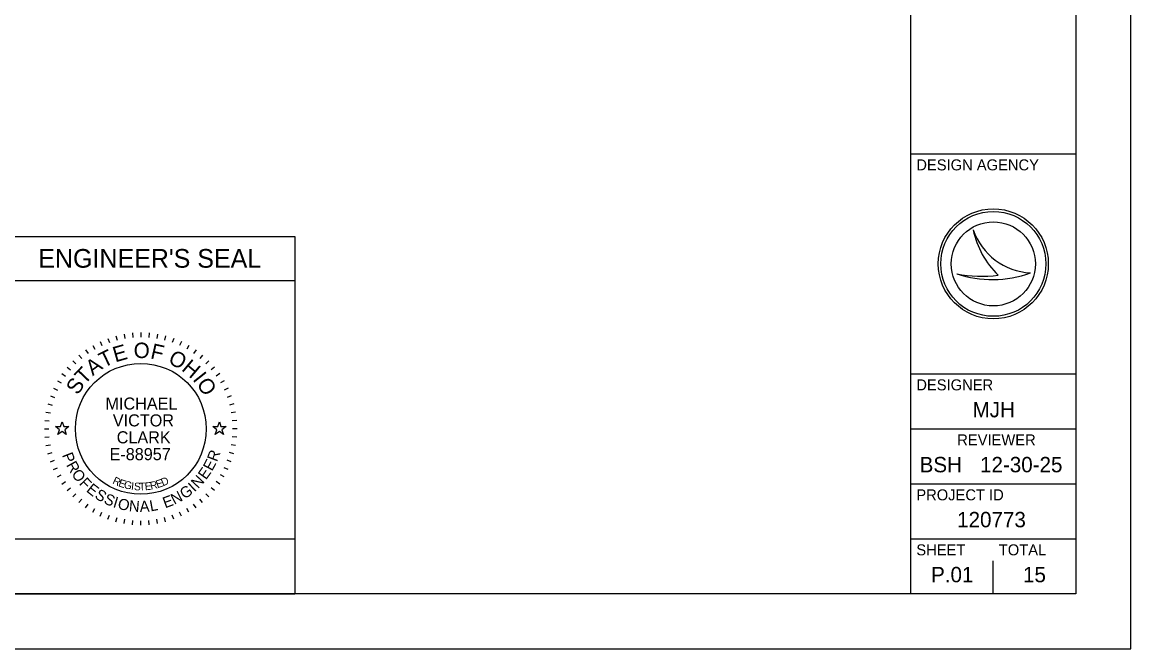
# Model space of a CAD drawing. Extents: x -7.9 to 76.1, y 0 to 22.
# Drawn here: x 23.92 to 34, y 0 to 5.7 of the extents above; entities that cross this region are included whole.
import ezdxf

# ---------------------------------------------------------------- set-up
doc = ezdxf.new("R2010")
doc.units = 0
for name, color, linetype in [('Default', 7, 'Continuous'), ('SH_Border', 7, 'Continuous'), ('SH_Cut_Line', 7, 'Continuous'), ('SH_Data', 7, 'Continuous')]:
    doc.layers.add(name, color=color, linetype=linetype)

msp = doc.modelspace()

# ---------------------------------------------------------------- linework, layer by layer
at = {"layer": 'Default'}
for p, q in [((24.701, 2.822), (24.714, 2.785)), ((24.774, 2.845), (24.784, 2.807)), ((24.848, 2.862), (24.855, 2.822)), ((24.924, 2.872), (24.927, 2.832)), ((25, 2.875), (25, 2.835)), ((25.076, 2.872), (25.073, 2.832)), ((25.152, 2.862), (25.145, 2.822)), ((25.226, 2.845), (25.216, 2.807)), ((25.299, 2.822), (25.286, 2.785)), ((24.563, 2.758), (24.583, 2.723)), ((24.63, 2.793), (24.647, 2.757)), ((25.37, 2.793), (25.353, 2.757)), ((25.437, 2.758), (25.417, 2.723)), ((24.438, 2.67), (24.463, 2.64)), ((24.498, 2.717), (24.521, 2.684)), ((25.502, 2.717), (25.479, 2.684)), ((25.562, 2.67), (25.537, 2.64)), ((24.33, 2.562), (24.36, 2.537)), ((24.381, 2.619), (24.41, 2.59)), ((25.619, 2.619), (25.59, 2.59)), ((25.67, 2.562), (25.64, 2.537)), ((24.242, 2.438), (24.277, 2.418)), ((24.283, 2.502), (24.316, 2.479)), ((25.717, 2.502), (25.684, 2.479)), ((25.758, 2.438), (25.723, 2.418)), ((24.207, 2.37), (24.243, 2.353)), ((25.793, 2.37), (25.757, 2.353)), ((24.155, 2.226), (24.193, 2.216)), ((24.178, 2.299), (24.215, 2.286)), ((25.822, 2.299), (25.785, 2.286)), ((25.845, 2.226), (25.807, 2.216)), ((24.138, 2.152), (24.178, 2.145)), ((25.862, 2.152), (25.822, 2.145)), ((24.128, 2.076), (24.168, 2.073)), ((25.872, 2.076), (25.832, 2.073)), ((24.125, 2), (24.165, 2)), ((24.128, 1.924), (24.168, 1.927)), ((25.872, 1.924), (25.832, 1.927)), ((25.875, 2), (25.835, 2)), ((24.138, 1.848), (24.178, 1.855)), ((25.862, 1.848), (25.822, 1.855)), ((24.155, 1.774), (24.193, 1.784)), ((24.178, 1.701), (24.215, 1.714)), ((25.822, 1.701), (25.785, 1.714)), ((25.845, 1.774), (25.807, 1.784)), ((24.207, 1.63), (24.243, 1.647)), ((25.793, 1.63), (25.757, 1.647)), ((24.242, 1.563), (24.277, 1.583)), ((24.283, 1.498), (24.316, 1.521)), ((25.717, 1.498), (25.684, 1.521)), ((25.758, 1.563), (25.723, 1.583)), ((24.33, 1.438), (24.36, 1.463)), ((25.67, 1.438), (25.64, 1.463)), ((24.381, 1.381), (24.41, 1.41)), ((24.438, 1.33), (24.463, 1.36)), ((24.498, 1.283), (24.521, 1.316)), ((25.502, 1.283), (25.479, 1.316)), ((25.562, 1.33), (25.537, 1.36)), ((25.619, 1.381), (25.59, 1.41)), ((24.563, 1.242), (24.583, 1.277)), ((24.63, 1.207), (24.647, 1.243)), ((24.701, 1.178), (24.714, 1.215)), ((25.299, 1.178), (25.286, 1.215)), ((25.37, 1.207), (25.353, 1.243)), ((25.437, 1.242), (25.417, 1.277)), ((24.774, 1.155), (24.784, 1.193)), ((24.848, 1.138), (24.855, 1.178)), ((24.924, 1.128), (24.927, 1.168)), ((25, 1.125), (25, 1.165)), ((25.076, 1.128), (25.073, 1.168)), ((25.152, 1.138), (25.145, 1.178)), ((25.226, 1.155), (25.216, 1.193))]:
    msp.add_line(p, q, dxfattribs=at)
for points in [[(24.224, 2.02), (24.271, 2.02), (24.285, 2.065), (24.299, 2.02), (24.346, 2.02), (24.308, 1.992), (24.323, 1.948), (24.285, 1.975), (24.247, 1.948), (24.262, 1.992)], [(25.654, 2.02), (25.701, 2.02), (25.715, 2.065), (25.729, 2.02), (25.776, 2.02), (25.738, 1.992), (25.753, 1.948), (25.715, 1.975), (25.677, 1.948), (25.692, 1.992)]]:
    msp.add_lwpolyline(points, close=True, dxfattribs=at)
msp.add_circle((25, 2), 0.595, dxfattribs=at)
at = {"layer": 'SH_Border'}
for p, q in [((32, 0.5), (32, 21.5)), ((32, 4.5), (33.5, 4.5)), ((32, 2.5), (33.5, 2.5)), ((32, 2), (33.5, 2)), ((32, 1.5), (33.5, 1.5)), ((32, 1), (33.5, 1))]:
    msp.add_line(p, q, dxfattribs=at)
msp.add_lwpolyline([(1.5, 21.5), (33.5, 21.5), (33.5, 0.5), (1.5, 0.5)], close=True, dxfattribs=at)
at = {"layer": 'SH_Cut_Line'}
msp.add_lwpolyline([(0, 0), (34, 0), (34, 22), (0, 22)], close=True, dxfattribs=at)
at = {"layer": 'SH_Data'}
for p, q in [((23.6, 3.75), (26.4, 3.75)), ((26.4, 3.75), (26.4, 0.5)), ((32.567, 3.81), (32.567, 3.81)), ((32.75, 3.5), (32.75, 3.5)), ((23.6, 3.35), (26.4, 3.35)), ((32.417, 3.41), (32.417, 3.41)), ((33.087, 3.419), (33.087, 3.419)), ((32.75, 0.5), (32.75, 0.8)), ((32.375, 0.675), (32.375, 0.675)), ((23.6, 0.5), (26.4, 0.5))]:
    msp.add_line(p, q, dxfattribs=at)
msp.add_lwpolyline([(23.6, 0.5), (23.6, 1), (26.4, 1), (26.4, 0.5)], close=True, dxfattribs=at)
for radius in [0.5, 0.477, 0.477, 0.382]:
    msp.add_circle((32.75, 3.5), radius, dxfattribs=at)
for centre, radius, start, end in [((33.116, 3.998), 0.58, 198.9257, 198.9319), ((33.347, 3.97), 0.796, 191.6379, 191.6421), ((33.116, 3.998), 0.58, 198.9319, 267.1657), ((33.347, 3.97), 0.796, 191.6421, 226.0947), ((32.739, 4.37), 1.013, 251.4576, 290.0832), ((32.648, 4.654), 1.266, 259.4964, 259.4995), ((32.739, 4.37), 1.013, 251.4527, 251.4576), ((32.648, 4.654), 1.266, 259.4995, 276.6672)]:
    msp.add_arc(centre, radius, start, end, dxfattribs=at)

# ---------------------------------------------------------------- texts
at = {"layer": 'Default'}
for s, height, rotation, p in [('T', 0.14, 25.7167, (24.662, 2.552)), ('E', 0.14, 15.7571, (24.768, 2.604)), ('O', 0.14, 359.7812, (24.935, 2.644)), ('F', 0.14, 347.4362, (25.081, 2.642)), ('A', 0.14, 36.4747, (24.563, 2.478)), ('O', 0.14, 332.2586, (25.24, 2.602)), ('H', 0.14, 319.9136, (25.363, 2.536)), ('T', 0.14, 46.4344, (24.488, 2.396)), ('I', 0.14, 308.367, (25.466, 2.448)), ('S', 0.14, 57.1924, (24.428, 2.301)), ('O', 0.14, 303.1491, (25.502, 2.409)), ('P', 0.1, 291.494, (24.282, 1.762)), ('E', 0.1, 61.9951, (25.648, 1.61)), ('R', 0.1, 69.2322, (25.692, 1.695)), ('R', 0.1, 298.7311, (24.319, 1.672)), ('O', 0.1, 306.4666, (24.365, 1.588)), ('E', 0.1, 54.758, (25.593, 1.531)), ('F', 0.1, 314.7068, (24.434, 1.498)), ('R', 0.07, 334.487, (24.737, 1.505)), ('E', 0.07, 341.04, (24.791, 1.48)), ('G', 0.07, 347.4752, (24.841, 1.462)), ('I', 0.07, 353.7858, (24.909, 1.447)), ('S', 0.07, 356.8926, (24.936, 1.443)), ('E', 0.07, 6.0117, (25.039, 1.441)), ('R', 0.07, 11.9184, (25.092, 1.447)), ('E', 0.07, 17.6836, (25.15, 1.46)), ('D', 0.07, 23.3052, (25.201, 1.477)), ('N', 0.1, 47.0224, (25.52, 1.451)), ('E', 0.1, 321.4393, (24.498, 1.435)), ('S', 0.1, 328.6764, (24.574, 1.375)), ('T', 0.07, 3.0061, (24.986, 1.439)), ('N', 0.1, 27.3113, (25.304, 1.308)), ('G', 0.1, 35.0469, (25.398, 1.357)), ('I', 0.1, 43.287, (25.487, 1.421)), ('S', 0.1, 335.9134, (24.656, 1.327)), ('I', 0.1, 343.1505, (24.741, 1.29)), ('O', 0.1, 346.8859, (24.784, 1.275)), ('N', 0.1, 355.1261, (24.889, 1.252)), ('A', 0.1, 2.8617, (24.992, 1.244)), ('L', 0.1, 10.0987, (25.089, 1.249)), ('E', 0.1, 20.0742, (25.221, 1.277))]:
    msp.add_text(s, height=height, rotation=rotation, dxfattribs=at).set_placement(p)
for s, p in [('MICHAEL', (24.679, 2.175)), ('VICTOR', (24.746, 2.022)), ('CLARK', (24.781, 1.868)), ('E-88957', (24.716, 1.715))]:
    msp.add_text(s, height=0.11, dxfattribs=at).set_placement(p)
at = {"layer": 'SH_Data'}
for s, height, p in [('DESIGN AGENCY', 0.1, (32.05, 4.35)), ("ENGINEER'S SEAL", 0.17, (24.068, 3.465)), ('DESIGNER', 0.1, (32.05, 2.35)), ('MJH', 0.14, (32.561, 2.105)), ('REVIEWER', 0.1, (32.422, 1.85)), ('BSH', 0.14, (32.08, 1.605)), ('12-30-25', 0.14, (32.629, 1.605)), ('PROJECT ID', 0.1, (32.05, 1.35)), ('120773', 0.14, (32.421, 1.105)), ('SHEET', 0.1, (32.05, 0.85)), ('TOTAL', 0.1, (32.8, 0.85)), ('P.01', 0.14, (32.184, 0.605)), ('15', 0.14, (33.02, 0.605))]:
    msp.add_text(s, height=height, dxfattribs=at).set_placement(p)

doc.saveas('drawing.dxf')
